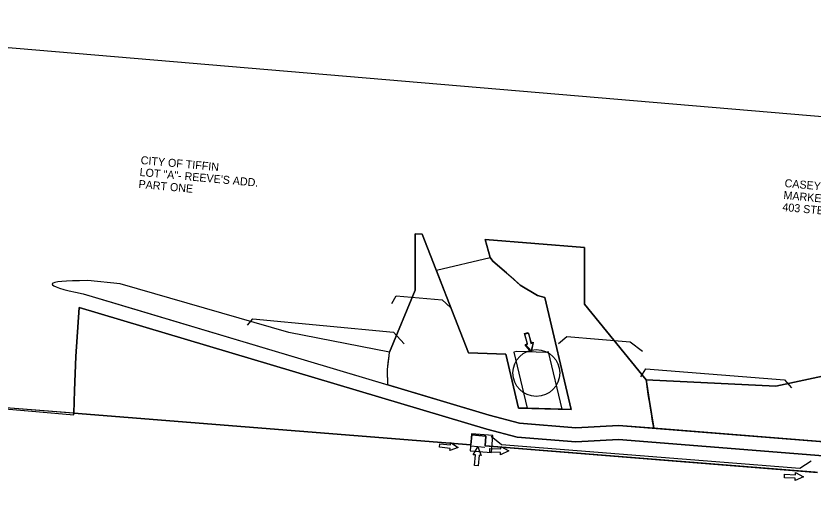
# Model space of a CAD drawing. Extents: x 20499351 to 20505779, y 7953198 to 7954637.
# Drawn here: x 20501297.9 to 20501580.1, y 7953921.8 to 7954095 of the extents above; entities that cross this region are included whole.
import ezdxf

# ---------------------------------------------------------------- set-up
doc = ezdxf.new("R2010")
doc.units = 0
for name, color, linetype in [('_CIVIL_CONSTRUCTION', 7, 'Continuous'), ('Contours Major', 7, 'Continuous'), ('Contours Minor', 7, 'Continuous'), ('Mulch', 7, 'Continuous'), ('NamedBoundary', 7, 'Continuous'), ('TL_GroundIntercept', 7, 'Continuous')]:
    doc.layers.add(name, color=color, linetype=linetype)

msp = doc.modelspace()

# ---------------------------------------------------------------- linework, layer by layer
at = {"layer": '_CIVIL_CONSTRUCTION'}
for p, q in [((20501477.97, 7953982.57), (20501479.19, 7953982.92)), ((20501477.97, 7953982.57), (20501479.19, 7953982.92)), ((20501479.01, 7953978.9), (20501477.97, 7953982.57)), ((20501479.01, 7953978.9), (20501477.97, 7953982.57)), ((20501478.04, 7953982.46), (20501479.28, 7953982.75)), ((20501478.92, 7953978.74), (20501478.04, 7953982.46)), ((20501479.19, 7953982.92), (20501480.23, 7953979.24)), ((20501479.19, 7953982.92), (20501480.23, 7953979.24)), ((20501479.28, 7953982.75), (20501480.16, 7953979.04)), ((20501478.24, 7953978.68), (20501479.01, 7953978.9)), ((20501478.24, 7953978.68), (20501479.01, 7953978.9)), ((20501480.16, 7953979.04), (20501480.93, 7953979.22)), ((20501480.93, 7953979.22), (20501480.2, 7953976.1)), ((20501480.23, 7953979.24), (20501481, 7953979.46)), ((20501480.23, 7953979.24), (20501481, 7953979.46)), ((20501481, 7953979.46), (20501480.4, 7953976.32)), ((20501481, 7953979.46), (20501480.4, 7953976.32)), ((20501478.15, 7953978.56), (20501478.92, 7953978.74)), ((20501480.2, 7953976.1), (20501478.15, 7953978.56)), ((20501480.4, 7953976.32), (20501478.24, 7953978.68)), ((20501480.4, 7953976.32), (20501478.24, 7953978.68)), ((20501447.77, 7953942.27), (20501447.89, 7953943.54)), ((20501451.57, 7953941.9), (20501447.77, 7953942.27)), ((20501447.89, 7953943.54), (20501451.69, 7953943.17)), ((20501454.48, 7953942.26), (20501451.49, 7953941.11)), ((20501451.69, 7953943.17), (20501451.77, 7953943.96)), ((20501451.77, 7953943.96), (20501454.48, 7953942.26)), ((20501459.75, 7953939.66), (20501461.42, 7953942.38)), ((20501461.42, 7953942.38), (20501462.6, 7953939.41)), ((20501469.51, 7953941.72), (20501469.53, 7953942.51)), ((20501469.53, 7953942.51), (20501472.35, 7953940.98)), ((20501451.49, 7953941.11), (20501451.57, 7953941.9)), ((20501460.54, 7953939.59), (20501459.75, 7953939.66)), ((20501460.21, 7953935.78), (20501460.54, 7953939.59)), ((20501461.81, 7953939.48), (20501461.48, 7953935.67)), ((20501462.6, 7953939.41), (20501461.81, 7953939.48)), ((20501465.65, 7953940.58), (20501465.69, 7953941.85)), ((20501469.46, 7953940.44), (20501465.65, 7953940.58)), ((20501465.69, 7953941.85), (20501469.51, 7953941.72)), ((20501472.35, 7953940.98), (20501469.44, 7953939.65)), ((20501469.44, 7953939.65), (20501469.46, 7953940.44)), ((20501461.48, 7953935.67), (20501460.21, 7953935.78)), ((20501569.94, 7953931.51), (20501570.01, 7953932.78)), ((20501573.75, 7953931.3), (20501569.94, 7953931.51)), ((20501570.01, 7953932.78), (20501573.82, 7953932.57)), ((20501576.65, 7953931.78), (20501573.71, 7953930.51)), ((20501573.71, 7953930.51), (20501573.75, 7953931.3)), ((20501573.82, 7953932.57), (20501573.87, 7953933.37)), ((20501573.87, 7953933.37), (20501576.65, 7953931.78))]:
    msp.add_line(p, q, dxfattribs=at)
at = {"layer": 'Contours Major'}
for p, q in [((20501321.61, 7953996.61), (20501332.04, 7953993.53)), ((20501332.04, 7953993.53), (20501465.46, 7953953.65)), ((20501319.04, 7953974.42), (20501320.22, 7953991.82)), ((20501318.58, 7953962.43), (20501319.04, 7953974.42)), ((20501318.33, 7953954.31), (20501318.58, 7953962.43)), ((20501478.89, 7953956.09), (20501475.79, 7953956.18)), ((20501458.95, 7953943.14), (20501318.33, 7953954.31)), ((20501318.33, 7953954.31), (20501318.33, 7953954.31)), ((20501491.3, 7953955.72), (20501478.89, 7953956.09)), ((20501580.88, 7953933.45), (20501463.93, 7953942.74))]:
    msp.add_line(p, q, dxfattribs=at)
for points in [[(20501441.7, 7954017.73), (20501439.25, 7954017.92), (20501439.18, 7953997.87), (20501430.14, 7953976), (20501394.53, 7953982.89), (20501334.72, 7954000.2), (20501323.26, 7954001.29)], [(20501465.71, 7954009.45), (20501466.73, 7954008.14), (20501471.59, 7954004.07), (20501476.4, 7953999.74), (20501482.47, 7953996.05), (20501485.06, 7953995.28), (20501494.41, 7953955.63), (20501475.79, 7953956.18), (20501471.26, 7953975.27), (20501458.08, 7953975.78), (20501441.7, 7954017.73)], [(20501730.38, 7953955.92), (20501723.34, 7953951.36), (20501686.7, 7953957.09), (20501670.21, 7953966.82), (20501612.04, 7953973.01), (20501604.26, 7953971.98), (20501566.93, 7953963.96), (20501521.05, 7953966.17), (20501499.17, 7953992.95), (20501499.21, 7954013.01), (20501463.96, 7954015.91), (20501465.71, 7954009.45)], [(20501475.79, 7953956.18), (20501471.26, 7953975.27), (20501458.08, 7953975.78), (20501446.75, 7954005.06), (20501465.71, 7954009.45), (20501466.73, 7954008.14), (20501471.59, 7954004.07), (20501476.4, 7953999.74), (20501482.47, 7953996.05), (20501485.06, 7953995.28), (20501494.41, 7953955.63), (20501491.3, 7953955.72)], [(20501320.22, 7953991.82), (20501320.18, 7953991.82), (20501464.54, 7953948.71), (20501475.28, 7953945.85), (20501496.07, 7953944.2), (20501511.18, 7953945), (20501604.37, 7953937.6), (20501728.43, 7953926.49)], [(20501318.33, 7953954.31), (20501318.33, 7953954.31), (20501318.33, 7953954.31), (20501318.33, 7953954.31)], [(20501465.46, 7953953.65), (20501476.2, 7953950.79), (20501496.14, 7953949.21), (20501511.25, 7953950.02), (20501604.78, 7953942.58), (20501728.75, 7953931.48)], [(20501463.93, 7953942.74), (20501464.21, 7953946.23), (20501459.23, 7953946.63), (20501458.95, 7953943.14)]]:
    msp.add_lwpolyline(points, dxfattribs=at)
msp.add_ellipse((20502428.49, 7953888.8), major_axis=(-1117.8, 111.26), ratio=0.014831, start_param=6.134556, end_param=6.424572, dxfattribs=at)
at = {"layer": 'Contours Minor'}
for p, q in [((20501485.06, 7953995.28), (20501494.41, 7953955.63)), ((20501319.04, 7953974.42), (20501320.18, 7953991.82)), ((20501318.58, 7953962.43), (20501319.04, 7953974.42)), ((20501475.79, 7953956.18), (20501471.26, 7953975.27)), ((20501429.51, 7953964.39), (20501429.39, 7953969.77)), ((20501318.31, 7953953.75), (20501318.58, 7953962.43)), ((20501465.46, 7953953.65), (20501429.51, 7953964.39)), ((20501252.3, 7953959.56), (20501318.31, 7953953.75)), ((20501458.95, 7953943.14), (20501254.33, 7953959.4)), ((20501478.89, 7953956.09), (20501475.79, 7953956.18)), ((20501478.89, 7953956.09), (20501475.79, 7953956.18)), ((20501491.3, 7953955.72), (20501478.89, 7953956.09)), ((20501494.41, 7953955.63), (20501491.3, 7953955.72)), ((20501463.89, 7953942.24), (20501458.91, 7953942.64)), ((20501581.69, 7953933.38), (20501463.93, 7953942.74))]:
    msp.add_line(p, q, dxfattribs=at)
for points in [[(20501429.39, 7953969.77), (20501429.39, 7953969.77), (20501429.99, 7953974.63), (20501430.14, 7953976), (20501439.18, 7953997.87), (20501439.25, 7954017.92), (20501441.7, 7954017.73)], [(20501441.7, 7954017.73), (20501458.08, 7953975.78), (20501471.26, 7953975.27), (20501475.79, 7953956.18), (20501494.41, 7953955.63), (20501485.06, 7953995.28), (20501482.47, 7953996.05), (20501476.4, 7953999.74), (20501471.59, 7954004.07), (20501466.73, 7954008.14), (20501465.71, 7954009.45)], [(20501465.71, 7954009.45), (20501463.96, 7954015.91), (20501499.21, 7954013.01), (20501499.17, 7953992.95), (20501521.05, 7953966.17), (20501522.01, 7953959.15), (20501523.71, 7953949.02)], [(20501475.79, 7953956.18), (20501471.26, 7953975.27), (20501458.08, 7953975.78), (20501446.75, 7954005.06), (20501465.71, 7954009.45), (20501466.73, 7954008.14), (20501471.59, 7954004.07), (20501476.4, 7953999.74), (20501482.47, 7953996.05), (20501485.06, 7953995.28), (20501494.41, 7953955.63), (20501491.3, 7953955.72)], [(20501471.26, 7953975.27), (20501458.08, 7953975.78), (20501446.75, 7954005.06), (20501465.71, 7954009.45), (20501466.73, 7954008.14), (20501471.59, 7954004.07), (20501473.99, 7954001.9), (20501476.4, 7953999.74), (20501482.47, 7953996.05), (20501485.06, 7953995.28)], [(20501430.92, 7953993.22), (20501432.53, 7953995.86), (20501448.73, 7953994.54), (20501451.74, 7953991.75)], [(20501320.18, 7953991.82), (20501320.18, 7953991.82), (20501464.54, 7953948.71), (20501475.28, 7953945.85), (20501496.07, 7953944.2), (20501511.18, 7953945), (20501604.37, 7953937.6), (20501728.43, 7953926.49)], [(20501379.84, 7953985.58), (20501381.67, 7953987.78), (20501431.51, 7953983.01), (20501435.26, 7953978.89)], [(20501489.99, 7953979), (20501492.92, 7953981.56), (20501515.35, 7953979.58), (20501519.74, 7953976.29)], [(20501491.3, 7953955.72), (20501486.47, 7953976.13), (20501485.5, 7953975.9), (20501475.15, 7953976.21), (20501474.17, 7953975.98), (20501478.89, 7953956.09)], [(20501519.16, 7953967.2), (20501520.84, 7953970.05), (20501570.02, 7953966.17), (20501572.44, 7953963.31)], [(20501511.25, 7953950.02), (20501496.14, 7953949.21), (20501476.2, 7953950.79), (20501465.46, 7953953.65)], [(20501523.71, 7953949.02), (20501511.25, 7953950.02)], [(20501463.93, 7953942.74), (20501464.21, 7953946.23), (20501459.23, 7953946.63), (20501458.95, 7953943.14)], [(20501466.09, 7953946.25), (20501469.75, 7953943.24), (20501575.44, 7953934.84), (20501579.44, 7953937.48)]]:
    msp.add_lwpolyline(points, dxfattribs=at)
msp.add_lwpolyline([(20501459.18, 7953947.04), (20501458.7, 7953941.05), (20501466.25, 7953940.46), (20501466.72, 7953946.44)], close=True, dxfattribs=at)
msp.add_circle((20501482.1, 7953968.6), 8.3, dxfattribs=at)
at = {"layer": 'Mulch'}
for p, q in [((20501321.61, 7953996.61), (20501326, 7953995.31)), ((20501326, 7953995.31), (20501429.51, 7953964.39)), ((20501522.38, 7953956.97), (20501522.12, 7953958.47)), ((20501522.52, 7953956.1), (20501522.38, 7953956.97))]:
    msp.add_line(p, q, dxfattribs=at)
for points in [[(20501429.69, 7953972.2), (20501429.79, 7953973.04), (20501429.99, 7953974.63), (20501430.14, 7953976), (20501394.53, 7953982.89), (20501334.72, 7954000.2), (20501323.26, 7954001.29), (20501323.26, 7954001.29)], [(20501604.37, 7953937.6), (20501511.18, 7953945), (20501496.07, 7953944.2), (20501475.28, 7953945.85), (20501464.54, 7953948.71), (20501320.18, 7953991.82), (20501319.04, 7953974.42), (20501318.58, 7953962.43), (20501318.33, 7953954.31), (20501458.95, 7953943.14), (20501459.23, 7953946.63), (20501464.21, 7953946.23), (20501463.93, 7953942.74), (20501581.69, 7953933.38)], [(20501429.39, 7953969.77), (20501429.69, 7953972.2)], [(20501521.63, 7953961.91), (20501521.48, 7953963), (20501521.4, 7953963.56), (20501521.24, 7953964.78), (20501521.05, 7953966.17), (20501566.93, 7953963.96), (20501604.26, 7953971.98), (20501612.04, 7953973.01), (20501670.21, 7953966.82), (20501686.7, 7953957.09), (20501723.34, 7953951.36), (20501730.38, 7953955.92)], [(20501429.4, 7953969.07), (20501429.39, 7953969.77)], [(20501429.42, 7953968.36), (20501429.4, 7953969.07)], [(20501429.51, 7953964.39), (20501429.47, 7953966.18), (20501429.44, 7953967.65), (20501429.42, 7953968.36)], [(20501522.04, 7953958.98), (20501521.95, 7953959.57), (20501521.86, 7953960.23), (20501521.75, 7953961.02), (20501521.63, 7953961.91)], [(20501522.12, 7953958.47), (20501522.04, 7953958.98)], [(20501728.75, 7953931.48), (20501604.78, 7953942.58), (20501523.71, 7953949.02), (20501523.17, 7953952.24), (20501522.86, 7953954.09), (20501522.52, 7953956.1)]]:
    msp.add_lwpolyline(points, dxfattribs=at)
msp.add_lwpolyline([(20501318.33, 7953954.31), (20501252.3, 7953959.56), (20501318.31, 7953953.75)], close=True, dxfattribs=at)
msp.add_ellipse((20502428.49, 7953888.8), major_axis=(-1117.8, 111.26), ratio=0.014831, start_param=6.134556, end_param=6.424572, dxfattribs=at)
at = {"layer": 'NamedBoundary'}
msp.add_lwpolyline([(20501161.33, 7954095.04), (20501136.01, 7953796.11), (20502073.14, 7953716.74), (20502098.46, 7954015.67)], close=True, dxfattribs=at)

# ---------------------------------------------------------------- texts
at = {"layer": 'TL_GroundIntercept'}
for s, height, p in [('CITY OF TIFFIN', 2.8346, (20501341.93, 7954042.62)), ('LOT "A"- REEVE\'S ADD.', 2.8346, (20501341.55, 7954038.39)), ('PART ONE', 2.835, (20501341.16, 7954034.15)), ("CASEY'S", 2.835, (20501569.91, 7954034.48)), ('MARKETING COMPANY', 2.8346, (20501569.52, 7954030.24)), ('403 STEPHANS STREET', 2.8346, (20501569.13, 7954026.01))]:
    msp.add_text(s, height=height, rotation=354.7645, dxfattribs=at).set_placement(p)

doc.saveas('drawing.dxf')
